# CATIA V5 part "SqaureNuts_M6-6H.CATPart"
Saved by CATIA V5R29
Part number: SquareNuts_M6-6H
Bounding box of the stored display mesh (mm): x -7 to 7, y -7 to 7, z -3 to 3
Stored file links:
  C:\Users\Administrator\Desktop\프로젝트\Boxfold\Bolt\SqaureNuts_M4-6H.CATPart
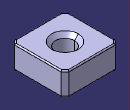
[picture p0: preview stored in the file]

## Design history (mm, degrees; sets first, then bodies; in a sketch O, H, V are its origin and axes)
Body1 (main body)
  Sketch1 on xy-plane, origin (0, 0, 0), H (1, 0, 0), V (0, 1, 0)
    line L1 (7, 7) -> (7, -7)
    line L2 (7, -7) -> (-7, -7)
    line L3 (-7, -7) -> (-7, 7)
    line L4 (-7, 7) -> (7, 7)
    length L3 = 14
    length L4 = 14
    vertical: L1 V, L3 V
    horizontal: L2 H, L4 H
    equidistance: L1 L3 O, L2 L4 O
  Pad1: profile Sketch1, direction (0, 0, 1), length 3, mirrored extent
  Sketch2 on end face of Pad1, origin (0.3753, 1.5089, 3), H (1, 0, 0), V (0, 1, 0)
    point P1 (-0.3753, -1.5089)
    reference projected line E1 (6.6247, -8.5089) -> (6.6247, 5.4911) from edge [face of Pad1 from Sketch1.L1 | end face of Pad1]
    reference projected line E2 (6.6247, 5.4911) -> (-7.3753, 5.4911) from edge [face of Pad1 from Sketch1.L4 | end face of Pad1]
    distance P1 E1 = 7
    distance E2 P1 = 7
  Hole1: placed by Sketch2, at (0, 0, 3) direction (0, 0, -1), diameter 4.917, through (limit type 3), threaded "M6", thread diameter 6, thread depth 6, pitch 1
  Chamfer1: length 1, angle 45, on face of Hole1; edge [face of Pad1 from Sketch1.L4 | face of Pad1 from Sketch1.L1]; edge [face of Pad1 from Sketch1.L3 | face of Pad1 from Sketch1.L4]; edge [face of Pad1 from Sketch1.L1 | face of Pad1 from Sketch1.L2]; edge [face of Pad1 from Sketch1.L2 | face of Pad1 from Sketch1.L3]
  Fillet1: radius 0.3, on edge [face of Pad1 from Sketch1.L3 | end face of Pad1]; edge [end face of Pad1 | face of Chamfer1] (x4); edge [face of Pad1 from Sketch1.L2 | end face of Pad1]; edge [face of Pad1 from Sketch1.L1 | end face of Pad1]; edge [face of Pad1 from Sketch1.L4 | end face of Pad1]; edge [start face of Pad1 | face of Pad1 from Sketch1.L3]; edge [start face of Pad1 | face of Chamfer1] (x4); edge [start face of Pad1 | face of Pad1 from Sketch1.L2]; edge [start face of Pad1 | face of Pad1 from Sketch1.L1]; edge [start face of Pad1 | face of Pad1 from Sketch1.L4]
